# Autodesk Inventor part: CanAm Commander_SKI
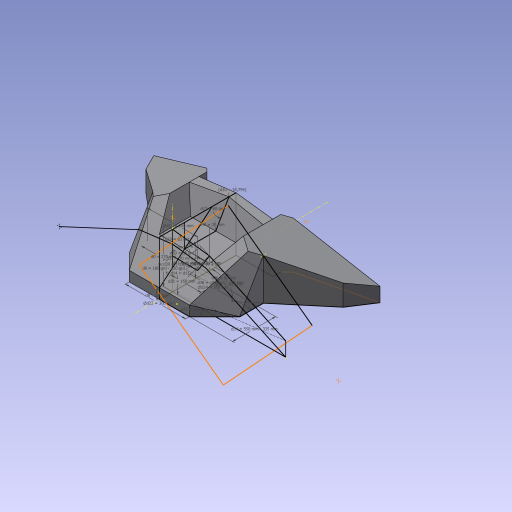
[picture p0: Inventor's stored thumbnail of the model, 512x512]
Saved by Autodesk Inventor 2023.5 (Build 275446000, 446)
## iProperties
Category: Vorlagen
Company: KAME engineering
Part Number: CanAm Commander_SKI
Material: Generisch
Document SubType Name: Modeling
Designer: wondraschek
Density: 1 g/cm^3
Appearance: Vorgabe
Stärke: 0
Breite: 0
Höhe: 0
Länge: 0
da: 0
di: 0
Title: Bauteilvorlage
Author: wondraschek
Comments: KAME engineering Lunzerstraße 89, 4030 Linz +43 732 6989 2474 www.kame.at
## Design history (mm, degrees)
sketch "Skizze3"
  geometry: L1 (0, 775.799)-(0, -205.388) reference; L2 (0, 315.971)-(183.976, 315.971) reference; L3 (183.976, 315.971)-(183.976, 356.128); L4 (183.976, 356.128)-(215.226, 386.642); L5 (215.226, 386.642)-(564.015, 470.928); L6 (564.015, 470.928)-(491.478, 359.217) reference; L7 (0, -65.218)-(150, -65.218) reference; L8 (150, -65.218)-(275, 59.782); L9 (0, 315.971)-(0, -65.218); L10 (275, 59.782)-(275, 177.57); L11 (275, 177.57)-(491.478, 359.217); L12 (-65, 169.782)-(65, 169.782); L13 (65, 169.782)-(65, 129.782); L14 (65, 129.782)-(-65, 129.782); L15 (-65, 129.782)-(-65, 169.782); L16 (-75, 149.782)-(75, 149.782); L17 (-87.5, 114.782)-(87.5, 114.782); L18 (87.5, 114.782)-(87.5, 184.782); L19 (87.5, 184.782)-(-87.5, 184.782); L20 (-87.5, 184.782)-(-87.5, 114.782); L21 (-87.5, 114.782)-(87.5, 184.782); L22 (87.5, 114.782)-(-87.5, 184.782); C1 r 5.5 at (-75, 149.782); C2 r 5.5 at (75, 149.782); 5 further points
  constraints: 42 end point, 5 horizontal, 5 midpoint, 5 perpendicular, 5 point on line, 4 parallel, 2 centre point, 2 coincident, 1 collinear, 1 equal radius, 1 vertical, 4 other
  dimensions: "d22" = 300 diameter of L7.end L1; "d24" = 550 diameter of L10 L1; "d25" = 135 deg angle of L7 L8; "d26" = 50 deg angle of L1 L11; "d34" = 215 distance between parallel lines of L7 L16; "d35" = 150 distance of L16.start L16.end; "d36" = 175 distance of L18.end L19.end; "d37" = 70 distance of L19.end L17.start; "d38" = 40 distance of L12.end L13.end; "d39" = 22.5 distance between parallel lines of L15 L20 (computed from d36); "d41" = 11 diameter of C1
sketch "Skizze2"
  geometry: L1 (0, -64.302)-(0, 385.813) reference; L2 (0, 0)-(-183.976, 247.411); L3 (0, 0)-(-564.015, 70.196); L4 (0, 0)-(0, 270); L5 (0, 270)-(-183.976, 247.411); L6 (-183.976, 247.411)-(-564.015, 70.196); L7 (-564.015, 70.196)-(-564.015, 0); L8 (-564.015, 0)-(0, 0); L9 (-183.976, 247.411)-(-125, 155); L10 (-125, 155)-(0, 155); L11 (-564.015, 0)-(-166.221, 185.494); L12 (-166.221, 185.494)-(0, 205.903); L13 (166.221, 185.494)-(0, 205.903); L14 (564.015, 0)-(166.221, 185.494); 3 further points
  constraints: 26 end point, 3 point on line, 2 parallel, 2 symmetric about line, 1 coincident, 1 horizontal, 1 perpendicular, 1 vertical, 1 vertical alignment
  dimensions: "d0" = 270 distance of L2.start L4.end; "d14" = 155 distance between parallel lines of L8 L10 (= d11); "d15" = 250 diameter of L9.end L1; "d29" = 83 deg angle of L4 L5; "d30" = 65 deg angle of L4 L6; "d31" = 63.61876 distance between parallel lines of L6 L11 (derived); "d32" = 63.61876 distance between parallel lines of L5 L12 (= d31)
sketch "Skizze4"
  geometry: L1 (-65.218, 0)-(-65.218, 270); L2 (-65.218, 270)-(315.971, 270); L3 (315.971, 0)-(315.971, 270); L4 (-65.218, 50)-(196.968, 270); L5 (59.916, 270)-(59.916, 155); L6 (59.916, 155)-(214.782, 155); L7 (214.782, 155)-(281.177, 270); L8 (315.971, 0)-(-65.218, 0) reference; 9 further points
  constraints: 14 end point, 6 point on line, 2 coincident, 2 perpendicular, 2 vertical, 1 horizontal, 4 other
  dimensions: "d8" = 50 dimension on L4.start; "d9" = 50 deg angle of L1 L4; "d10" = 34.7936 distance from line of L7.end L3 (derived); "d11" = 155 distance of the line from the sketch origin of L6; "d13" = 60 deg angle of L2 L7; "d40" = 30 horizontal distance of point (184.782, 0) L6.end
extrude "Extrusion1" new body sketch "Skizze3" stored distance "d1" = 10; taper "d2" = 0 deg
extrude "Extrusion3" sketch "Skizze2" extent not by distance; stored distance "d6" = 0; taper "d7" = 0 deg
extrude "Extrusion4" cut sketch "Skizze4" extent not by distance; stored distance "d16" = 0; taper "d17" = 0 deg
workplane "Arbeitsebene1"
extrude "Extrusion5" cut sketch "Skizze4" stored distance "d19" = 10; taper "d20" = 0 deg
workplane "Arbeitsebene2"
sketch "Skizze5"
  geometry: 1 further point
workplane "Arbeitsebene3"
workplane "Arbeitsebene5"
workplane "Arbeitsebene6"
sketch "Skizze6"
  geometry: L1 (0, -224.863)-(378.119, -224.863); L2 (378.119, -224.863)-(378.119, 311.653); L3 (378.119, 311.653)-(0, 311.653); L4 (0, 311.653)-(0, -224.863); 2 further points
  constraints: 8 end point, 2 parallel, 1 horizontal, 1 perpendicular, 1 point on line
extrude "Extrusion6" cut sketch "Skizze6" extent not by distance; stored distance "d27" = 0; taper "d28" = 0 deg
mirror "Spiegeln2"
feature "Trennen1"
node "Volumenkörper1"
other parameters: "Stärke" = 0 [user parameter], "Breite" = 0 [user parameter], "Höhe" = 0 [user parameter], "Länge" = 0 [user parameter], "da" = 0 [user parameter], "di" = 0 [user parameter], "d18" = 90 deg
